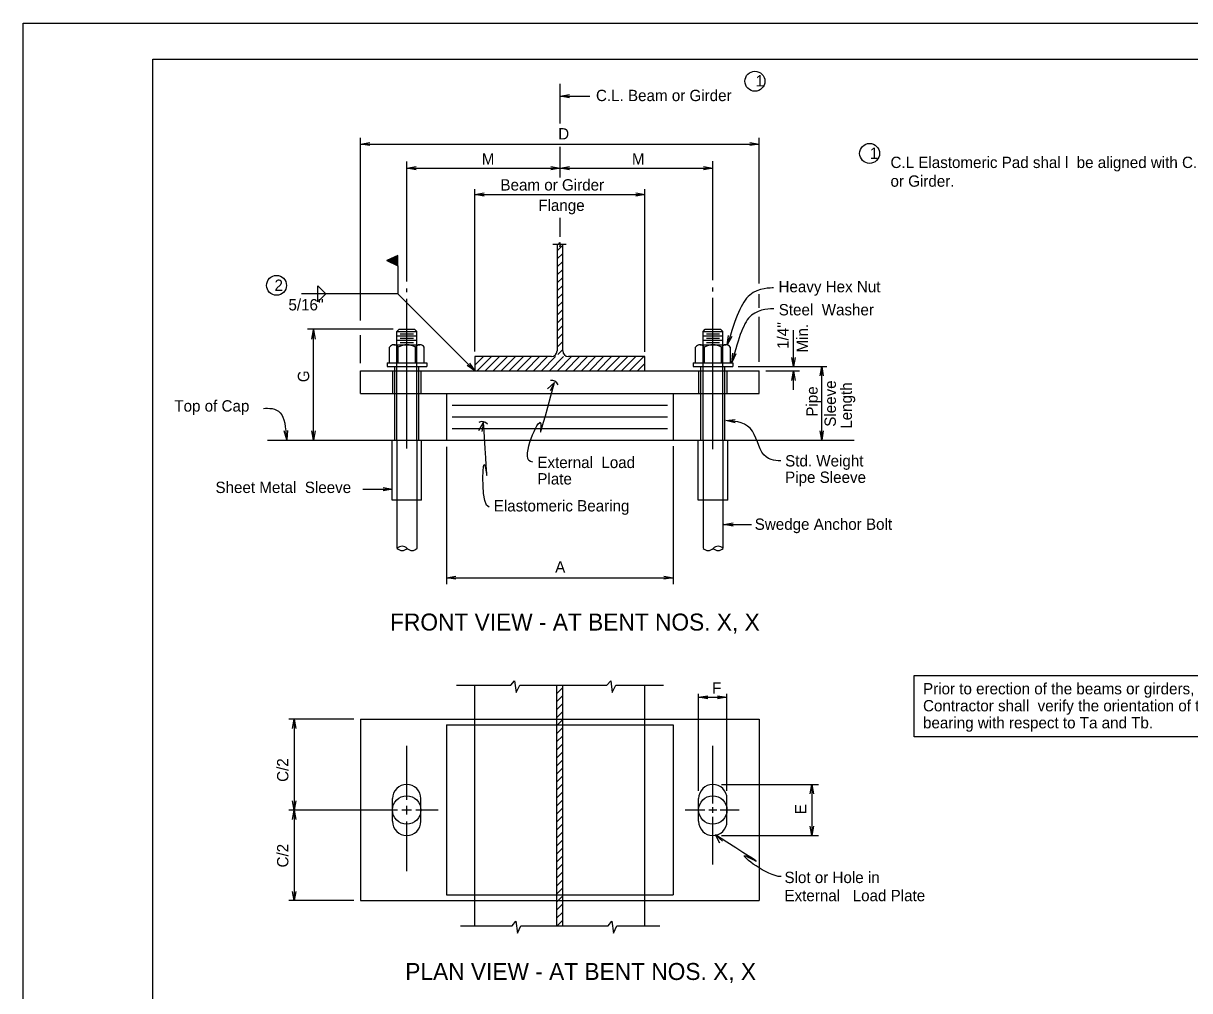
# Model space of a CAD drawing. Extents: x 113 to 232, y -103 to -27.
# Drawn here: x 176.59 to 185.16, y -74.86 to -67.75 of the extents above; entities that cross this region are included whole.
import ezdxf

# ---------------------------------------------------------------- set-up
doc = ezdxf.new("R2010")
doc.units = 0
for name, color, linetype in [('1', 7, 'Continuous'), ('B_Border', 7, 'Continuous'), ('B_Dimension', 7, 'Continuous'), ('B_No_Plot', 7, 'Continuous')]:
    doc.layers.add(name, color=color, linetype=linetype)

msp = doc.modelspace()

# ---------------------------------------------------------------- linework, layer by layer
at = {"layer": '1'}
for p, q in [((180.5342, -68.4846), (180.5342, -68.1923)), ((180.5342, -68.2835), (180.7515, -68.2835)), ((179.067, -69.933), (179.067, -68.5907)), ((181.997, -69.6603), (181.997, -68.5907)), ((179.067, -68.6354), (181.997, -68.6354)), ((180.5342, -68.8825), (180.5342, -68.6555)), ((179.407, -69.6472), (179.407, -68.7631)), ((181.657, -69.6364), (181.657, -68.7621)), ((179.407, -68.8121), (180.5342, -68.8121)), ((180.5342, -68.8121), (181.657, -68.8121)), ((179.907, -70.162), (179.907, -68.9673)), ((179.907, -69.0068), (181.1584, -69.0068)), ((181.157, -70.1644), (181.157, -68.9673)), ((180.5342, -69.3185), (180.5342, -69.178)), ((180.5238, -69.3728), (180.5318, -69.3587)), ((180.5318, -69.3587), (180.5318, -69.3918)), ((180.4803, -69.3728), (180.5238, -69.3728)), ((180.5113, -69.3728), (180.5113, -70.1571)), ((180.5318, -69.3918), (180.5379, -69.3728)), ((180.5379, -69.3728), (180.5783, -69.3728)), ((180.5528, -70.1571), (180.5528, -69.3728)), ((179.3414, -69.4552), (179.2604, -69.4929)), ((179.2604, -69.4929), (179.3414, -69.5306)), ((179.3414, -69.4552), (179.3414, -69.4545)), ((179.3414, -69.5306), (179.3414, -69.4552)), ((179.3414, -69.5306), (179.3414, -69.5611)), ((179.3414, -69.5611), (179.3414, -69.7373)), ((178.7515, -69.7963), (178.7515, -69.6783)), ((178.7515, -69.6783), (178.8105, -69.7373)), ((179.407, -69.7257), (179.407, -69.6982)), ((181.657, -69.7187), (181.657, -69.6913)), ((179.3414, -69.7373), (178.6323, -69.7373)), ((178.8105, -69.7373), (178.7515, -69.7963)), ((179.907, -70.3029), (179.3414, -69.7373)), ((179.407, -70.8751), (179.407, -69.7727)), ((181.657, -70.88), (181.657, -69.7658)), ((181.997, -69.8388), (181.997, -69.739)), ((181.997, -70.2356), (181.997, -69.907)), ((179.3064, -69.9975), (178.6752, -69.9975)), ((178.7213, -70.8134), (178.7213, -70.0011)), ((179.067, -70.2474), (179.067, -70.0414)), ((179.3504, -69.9975), (179.3341, -70.0138)), ((179.3341, -70.111), (179.3341, -70.0138)), ((179.3341, -70.0138), (179.4799, -70.0138)), ((179.3341, -70.0462), (179.4799, -70.0462)), ((179.3504, -69.9975), (179.4636, -69.9975)), ((179.3584, -70.0302), (179.4556, -70.0302)), ((179.4636, -69.9975), (179.4799, -70.0138)), ((179.4799, -70.111), (179.4799, -70.0138)), ((181.5841, -70.0138), (181.6004, -69.9975)), ((181.5841, -70.0138), (181.7299, -70.0138)), ((181.5841, -70.111), (181.5841, -70.0138)), ((181.5841, -70.0138), (181.7299, -70.0138)), ((181.5841, -70.0462), (181.7299, -70.0462)), ((181.6004, -69.9975), (181.7136, -69.9975)), ((181.6084, -70.0302), (181.7056, -70.0302)), ((181.7136, -69.9975), (181.7299, -70.0138)), ((181.7299, -70.111), (181.7299, -70.0138)), ((182.2483, -70.272), (182.2483, -70.0031)), ((179.2797, -70.2448), (179.2797, -70.1293)), ((179.3118, -70.111), (179.5025, -70.111)), ((179.3341, -70.0786), (179.4799, -70.0786)), ((179.3341, -70.8134), (179.3341, -70.111)), ((179.344, -70.2448), (179.344, -70.1293)), ((179.3584, -70.0626), (179.4556, -70.0626)), ((179.3584, -70.0949), (179.4556, -70.0949)), ((179.4702, -70.2448), (179.4702, -70.1293)), ((179.4799, -70.8134), (179.4799, -70.111)), ((179.5348, -70.2448), (179.5348, -70.1293)), ((181.5297, -70.2448), (181.5297, -70.1293)), ((181.5618, -70.111), (181.7525, -70.111)), ((181.5841, -70.0786), (181.7299, -70.0786)), ((181.5841, -70.8134), (181.5841, -70.111)), ((181.594, -70.2448), (181.594, -70.1293)), ((181.6084, -70.0626), (181.7056, -70.0626)), ((181.6084, -70.0949), (181.7056, -70.0949)), ((181.7202, -70.2448), (181.7202, -70.1293)), ((181.7299, -70.8134), (181.7299, -70.111)), ((181.7848, -70.2448), (181.7848, -70.1293)), ((180.4696, -70.1987), (179.907, -70.1987)), ((179.907, -70.1987), (179.907, -70.3029)), ((181.157, -70.1987), (180.5944, -70.1987)), ((181.157, -70.3029), (181.157, -70.1987)), ((179.067, -70.4696), (179.067, -70.3029)), ((179.067, -70.3029), (181.997, -70.3029)), ((179.2612, -70.2448), (179.5528, -70.2448)), ((179.2612, -70.2448), (179.2612, -70.2708)), ((179.2612, -70.2708), (179.5528, -70.2708)), ((179.3029, -70.4696), (179.3029, -70.3042)), ((179.3185, -70.3042), (179.3185, -70.2712)), ((179.3185, -70.4696), (179.3185, -70.3042)), ((179.4955, -70.3042), (179.4955, -70.2712)), ((179.4955, -70.4694), (179.4955, -70.3042)), ((179.5111, -70.4696), (179.5111, -70.3042)), ((179.5528, -70.2448), (179.5528, -70.2708)), ((181.5112, -70.2448), (181.8028, -70.2448)), ((181.5112, -70.2448), (181.5112, -70.2708)), ((181.5112, -70.2708), (181.8028, -70.2708)), ((181.5529, -70.4705), (181.5529, -70.3037)), ((181.5685, -70.3037), (181.5685, -70.2704)), ((181.5685, -70.4705), (181.5685, -70.3037)), ((181.7455, -70.3037), (181.7455, -70.2714)), ((181.7455, -70.4715), (181.7455, -70.3067)), ((181.7611, -70.4715), (181.7611, -70.3067)), ((181.8028, -70.2448), (181.8028, -70.2708)), ((181.8428, -70.2708), (182.494, -70.2708)), ((181.997, -70.4696), (181.997, -70.3029)), ((182.0449, -70.3029), (182.2939, -70.3029)), ((182.2483, -70.4429), (182.2483, -70.3053)), ((182.4563, -70.8134), (182.4563, -70.2708)), ((179.067, -70.4696), (181.997, -70.4696)), ((179.3185, -70.8134), (179.3185, -70.4696)), ((179.4955, -70.8134), (179.4955, -70.4694)), ((179.6986, -70.4696), (179.6986, -70.8134)), ((181.3654, -70.4696), (181.3654, -70.8134)), ((181.5685, -70.8134), (181.5685, -70.4705)), ((181.7455, -70.8134), (181.7455, -70.4715)), ((179.7404, -70.5556), (181.3236, -70.5556)), ((179.7404, -70.6416), (181.3236, -70.6416)), ((179.7404, -70.7275), (181.3236, -70.7275)), ((178.3829, -70.8134), (182.6957, -70.8134)), ((179.2985, -71.2537), (179.2985, -70.8134)), ((179.3341, -70.8134), (179.3341, -71.2537)), ((179.4799, -70.8134), (179.4799, -71.2537)), ((179.5155, -71.2537), (179.5155, -70.8134)), ((181.5485, -71.2537), (181.5485, -70.8134)), ((181.5841, -70.8134), (181.5841, -71.2537)), ((181.7299, -70.8134), (181.7299, -71.2537)), ((181.7655, -71.2537), (181.7655, -70.8134)), ((179.6986, -70.8609), (179.6986, -71.8713)), ((181.3654, -70.8564), (181.3654, -71.8713)), ((179.0841, -71.1729), (179.3001, -71.1729)), ((179.5155, -71.2537), (179.2985, -71.2537)), ((179.3341, -71.2537), (179.3341, -71.6102)), ((179.4799, -71.2537), (179.4799, -71.6101)), ((181.7655, -71.2537), (181.5485, -71.2537)), ((181.5841, -71.2537), (181.5841, -71.6067)), ((181.7299, -71.2537), (181.7299, -71.6069)), ((181.7368, -71.4334), (181.9395, -71.4334)), ((179.6986, -71.8237), (181.3654, -71.8237)), ((179.7723, -72.6138), (180.1718, -72.6138)), ((179.9058, -74.3826), (179.9058, -72.6137)), ((180.2363, -72.6138), (180.8779, -72.6138)), ((180.5099, -74.3826), (180.5099, -72.6137)), ((180.5516, -72.6137), (180.5516, -74.3826)), ((180.9425, -72.6138), (181.2935, -72.6138)), ((181.1558, -74.3826), (181.1558, -72.6137)), ((181.5516, -73.3897), (181.5516, -72.6771)), ((181.5516, -72.7033), (181.7599, -72.7033)), ((181.7599, -73.3897), (181.7599, -72.6771)), ((179.0178, -72.8649), (178.5404, -72.8649)), ((178.5775, -72.8649), (178.5775, -73.5332)), ((179.0658, -72.8649), (179.0658, -74.1983)), ((179.0658, -72.8649), (179.9032, -72.8649)), ((179.9032, -72.8649), (181.158, -72.8649)), ((181.158, -72.8649), (181.9958, -72.8649)), ((181.158, -72.8649), (181.9958, -72.8649)), ((181.9958, -72.8649), (181.9958, -74.1983)), ((179.6974, -72.9066), (179.6974, -74.1566)), ((179.6974, -72.9066), (181.3641, -72.9066)), ((181.3641, -72.9066), (181.3641, -74.1566)), ((179.4058, -73.4558), (179.4058, -73.0609)), ((181.6558, -73.4837), (181.6558, -73.0609)), ((181.7195, -73.3441), (182.433, -73.3441)), ((182.3846, -73.3441), (182.3846, -73.7191)), ((179.3016, -73.6149), (179.3016, -73.4483)), ((179.5099, -73.6149), (179.5099, -73.4483)), ((181.5516, -73.6149), (181.5516, -73.4483)), ((181.7599, -73.6149), (181.7599, -73.4483)), ((178.5404, -73.5316), (179.3383, -73.5316)), ((178.5775, -73.5332), (178.5775, -74.1983)), ((179.3697, -73.5316), (179.441, -73.5316)), ((179.4058, -73.5644), (179.4058, -73.501)), ((179.4723, -73.5316), (179.5099, -73.5316)), ((179.5099, -73.5316), (179.6369, -73.5316)), ((181.452, -73.5316), (181.5962, -73.5316)), ((181.6274, -73.5316), (181.6866, -73.5316)), ((181.6558, -73.5532), (181.6558, -73.5114)), ((181.7109, -73.5316), (181.7599, -73.5316)), ((181.7599, -73.5316), (181.8498, -73.5316)), ((179.4058, -73.9814), (179.4058, -73.6157)), ((181.6558, -73.9325), (181.6558, -73.5827)), ((181.7195, -73.7191), (182.433, -73.7191)), ((179.6974, -74.1566), (181.3641, -74.1566)), ((179.0178, -74.1983), (178.5404, -74.1983)), ((179.0658, -74.1983), (179.9032, -74.1983)), ((179.9032, -74.1983), (181.1545, -74.1983)), ((181.1545, -74.1983), (181.9958, -74.1983)), ((179.8006, -74.3826), (180.1798, -74.3826)), ((180.2444, -74.3826), (180.8859, -74.3826)), ((180.9505, -74.3826), (181.2653, -74.3826))]:
    msp.add_line(p, q, dxfattribs=at)
for points in [[(180.5164, -69.4162), (180.5476, -69.385)], [(180.5164, -69.4752), (180.5476, -69.444)], [(179.2614, -69.4933), (179.2614, -69.4925)], [(179.2657, -69.4954), (179.2657, -69.4905)], [(179.27, -69.4974), (179.27, -69.4885)], [(179.2743, -69.4993), (179.2743, -69.4865)], [(179.2786, -69.5013), (179.2786, -69.4845)], [(179.2829, -69.5033), (179.2829, -69.4825)], [(179.2873, -69.5054), (179.2873, -69.4805)], [(179.2915, -69.5074), (179.2915, -69.4785)], [(179.2958, -69.5093), (179.2958, -69.4765)], [(179.3002, -69.5113), (179.3002, -69.4745)], [(179.3044, -69.5133), (179.3044, -69.4725)], [(179.3088, -69.5154), (179.3088, -69.4705)], [(179.3131, -69.5174), (179.3131, -69.4684)], [(179.3173, -69.5193), (179.3173, -69.4664)], [(179.3217, -69.5213), (179.3217, -69.4644)], [(179.3259, -69.5233), (179.3259, -69.4624)], [(179.3303, -69.5254), (179.3303, -69.4605)], [(179.3346, -69.5274), (179.3346, -69.4584)], [(179.3388, -69.5293), (179.3388, -69.4564)], [(180.5164, -69.5341), (180.5476, -69.5029)], [(180.5164, -69.593), (180.5476, -69.5618)], [(180.5164, -69.6519), (180.5476, -69.6207)], [(180.5164, -69.7108), (180.5476, -69.6797)], [(180.5164, -69.7697), (180.5476, -69.7386)], [(180.5164, -69.8287), (180.5476, -69.7975)], [(180.5164, -69.8876), (180.5476, -69.8564)], [(180.5164, -69.9465), (180.5476, -69.9153)], [(180.5164, -70.0054), (180.5476, -69.9742)], [(180.5164, -70.0643), (180.5476, -70.0332)], [(180.5164, -70.1232), (180.5476, -70.0921)], [(179.907, -70.2613), (179.9696, -70.1987)], [(179.907, -70.2024), (179.9107, -70.1987)], [(179.9243, -70.3029), (180.0285, -70.1987)], [(179.9833, -70.3029), (180.0874, -70.1987)], [(180.0422, -70.3029), (180.1463, -70.1987)], [(180.1011, -70.3029), (180.2053, -70.1987)], [(180.16, -70.3029), (180.2642, -70.1987)], [(180.2189, -70.3029), (180.3231, -70.1987)], [(180.2778, -70.3029), (180.382, -70.1987)], [(180.3368, -70.3029), (180.441, -70.1987)], [(180.3957, -70.3029), (180.4999, -70.1987)], [(180.4547, -70.3029), (180.5588, -70.1987)], [(180.5136, -70.3029), (180.6178, -70.1987)], [(180.5164, -70.1822), (180.5476, -70.151)], [(180.5725, -70.3029), (180.6767, -70.1987)], [(180.6314, -70.3029), (180.7356, -70.1987)], [(180.6903, -70.3029), (180.7945, -70.1987)], [(180.7493, -70.3029), (180.8535, -70.1987)], [(180.8082, -70.3029), (180.9123, -70.1987)], [(180.8672, -70.3028), (180.9713, -70.1987)], [(180.926, -70.3029), (181.0303, -70.1987)], [(180.985, -70.3029), (181.0892, -70.1987)], [(181.0439, -70.3029), (181.1481, -70.1987)], [(179.4178, -70.3029), (179.4178, -70.3029)], [(179.5356, -70.3029), (179.5356, -70.3029)], [(179.5946, -70.3029), (179.5946, -70.3029)], [(181.1028, -70.3029), (181.157, -70.2487)], [(181.5504, -70.3029), (181.5504, -70.3029)], [(180.1718, -72.6138), (180.1991, -72.5813), (180.2112, -72.668), (180.2363, -72.6138)], [(180.8779, -72.6138), (180.9053, -72.5813), (180.9173, -72.668), (180.9425, -72.6138)], [(180.5099, -72.6758), (180.5516, -72.6342)], [(180.5099, -72.7347), (180.5516, -72.6931)], [(180.5099, -72.7937), (180.5516, -72.752)], [(180.5099, -72.8526), (180.5516, -72.8109)], [(180.5099, -72.9115), (180.5516, -72.8699)], [(180.5099, -72.9704), (180.5516, -72.9288)], [(180.5099, -73.0293), (180.5516, -72.9878)], [(180.5099, -73.0883), (180.5516, -73.0467)], [(180.5099, -73.1472), (180.5516, -73.1056)], [(180.5099, -73.2061), (180.5516, -73.1645)], [(180.5099, -73.265), (180.5516, -73.2234)], [(180.5099, -73.324), (180.5516, -73.2823)], [(180.5099, -73.3829), (180.5515, -73.3413)], [(180.5099, -73.4418), (180.5516, -73.4003)], [(180.5099, -73.5008), (180.5516, -73.4592)], [(180.5099, -73.5597), (180.5516, -73.5181)], [(180.5099, -73.6186), (180.5516, -73.577)], [(180.5099, -73.6775), (180.5516, -73.6359)], [(180.5099, -73.7364), (180.5516, -73.6948)], [(180.5099, -73.7953), (180.5516, -73.7538)], [(180.5099, -73.8543), (180.5516, -73.8127)], [(180.5099, -73.9133), (180.5516, -73.8716)], [(180.5099, -73.9722), (180.5516, -73.9306)], [(180.5099, -74.0311), (180.5516, -73.9895)], [(180.5099, -74.09), (180.5516, -74.0484)], [(180.5099, -74.1489), (180.5516, -74.1073)], [(180.5099, -74.2078), (180.5516, -74.1663)], [(180.5099, -74.2668), (180.5516, -74.2252)], [(180.5099, -74.3257), (180.5516, -74.2841)], [(180.1798, -74.3826), (180.2072, -74.3501), (180.2193, -74.4368), (180.2444, -74.3826)], [(180.5099, -74.3846), (180.5516, -74.343)], [(180.8859, -74.3826), (180.9133, -74.3501), (180.9253, -74.4368), (180.9505, -74.3826)]]:
    msp.add_lwpolyline(points, dxfattribs=at)
msp.add_lwpolyline([(183.1366, -72.5423), (186.0774, -72.5423), (186.0774, -72.9933), (183.1366, -72.9933)], close=True, dxfattribs=at)
for centre, radius in [((181.9655, -68.1738), 0.0733), ((182.8086, -68.7045), 0.0733), ((178.4489, -69.6745), 0.0733), ((179.4058, -73.5316), 0.1042), ((181.6558, -73.5316), 0.1042)]:
    msp.add_circle(centre, radius, dxfattribs=at)
for centre, radius, start, end in [((179.3119, -70.1484), 0.0375, 30.80861, 149.1914), ((179.4071, -70.229), 0.118, 57.68982, 122.31018), ((179.5025, -70.1486), 0.0376, 30.95728, 149.04272), ((181.5619, -70.1484), 0.0375, 30.80861, 149.1914), ((181.6571, -70.229), 0.118, 57.68982, 122.31018), ((181.7525, -70.1486), 0.0376, 30.95728, 149.04272), ((180.4696, -70.157), 0.0417, 270, 360), ((180.5945, -70.157), 0.0417, 180, 270), ((180.4706, -70.4244), 0.0513, 21.6992, 99.92259), ((179.9606, -70.7273), 0.0513, 40.39617, 118.61956), ((179.3722, -71.6433), 0.0504, 43.71346, 136.28654), ((181.6951, -71.6433), 0.0504, 43.71346, 136.28654), ((179.3722, -71.5736), 0.0504, 223.71346, 316.28654), ((179.4451, -71.5736), 0.0504, 223.71346, 316.28654), ((181.6222, -71.5736), 0.0504, 223.71346, 316.28654), ((181.6951, -71.5736), 0.0504, 223.71346, 316.28654), ((179.4058, -73.4482), 0.1042, 0, 180), ((181.6558, -73.4482), 0.1042, 0, 180), ((179.4058, -73.6149), 0.1042, 180, 0), ((181.6558, -73.6149), 0.1042, 180, 0)]:
    msp.add_arc(centre, radius, start, end, dxfattribs=at)
for points in [[(182.1019, -69.6937), (182.0853, -69.6931), (181.8981, -69.6902), (181.8273, -69.9102), (181.7627, -70.111)], [(182.1051, -69.8477), (182.0888, -69.8471), (181.9114, -69.8404), (181.8504, -70.0495), (181.7959, -70.2411)], [(180.3319, -70.9738), (180.23, -70.9738), (180.4923, -70.3881), (180.3319, -70.9738), (180.4923, -70.3881)], [(178.3524, -70.579), (178.3878, -70.5763), (178.5018, -70.5769), (178.5146, -70.7135), (178.5237, -70.8101)], [(180.0116, -71.3059), (179.9534, -71.3025), (179.9698, -70.6813), (180.0116, -71.3059), (179.9698, -70.6813)], [(182.1567, -70.9637), (182.1399, -70.9649), (182.0023, -70.971), (181.9673, -70.6785), (181.7968, -70.6712), (181.7516, -70.6692)], [(182.1587, -74.0218), (182.0508, -74.0188), (181.6756, -73.7152), (182.1587, -74.0218), (181.6756, -73.7152)]]:
    msp.add_open_spline(points, degree=3, dxfattribs=at)
at = {"layer": 'B_Border'}
for p, q in [((177.539, -68.0117), (198.6157, -68.0117)), ((177.539, -81.7084), (177.539, -68.0117)), ((177.5397, -81.7077), (177.5397, -68.0117))]:
    msp.add_line(p, q, dxfattribs=at)
at = {"layer": 'B_Dimension'}
for points in [[(180.6025, -68.2956), (180.5342, -68.2835), (180.6025, -68.2715)], [(179.1353, -68.6474), (179.067, -68.6354), (179.1353, -68.6233)], [(181.9287, -68.6233), (181.997, -68.6354), (181.9287, -68.6474)], [(179.4753, -68.8242), (179.407, -68.8121), (179.4753, -68.8001)], [(180.4659, -68.8001), (180.5342, -68.8121), (180.4659, -68.8242)], [(180.6025, -68.8242), (180.5342, -68.8121), (180.6025, -68.8001)], [(181.5887, -68.8001), (181.657, -68.8121), (181.5887, -68.8242)], [(179.9753, -69.0188), (179.907, -69.0068), (179.9753, -68.9947)], [(181.0901, -68.9947), (181.1584, -69.0068), (181.0901, -69.0188)], [(178.7092, -70.0694), (178.7213, -70.0011), (178.7333, -70.0694)], [(181.7951, -70.0496), (181.7627, -70.111), (181.7722, -70.0422)], [(181.8262, -70.1787), (181.7959, -70.2411), (181.803, -70.1721)], [(182.2604, -70.2037), (182.2483, -70.272), (182.2363, -70.2037)], [(179.8672, -70.2461), (179.907, -70.3029), (179.8502, -70.2631)], [(182.2363, -70.3736), (182.2483, -70.3053), (182.2604, -70.3736)], [(182.4442, -70.3391), (182.4563, -70.2708), (182.4683, -70.3391)], [(180.4408, -70.4347), (180.4923, -70.3881), (180.4599, -70.4495)], [(179.9361, -70.7419), (179.9698, -70.6813), (179.9588, -70.7498)], [(181.8194, -70.6842), (181.7516, -70.6692), (181.8204, -70.6601)], [(178.5293, -70.741), (178.5237, -70.8101), (178.5053, -70.7432)], [(178.7333, -70.7451), (178.7213, -70.8134), (178.7092, -70.7451)], [(182.4683, -70.7451), (182.4563, -70.8134), (182.4442, -70.7451)], [(179.2317, -71.1609), (179.3001, -71.1729), (179.2317, -71.185)], [(181.8051, -71.4455), (181.7368, -71.4334), (181.8051, -71.4214)], [(179.767, -71.8357), (179.6986, -71.8237), (179.767, -71.8116)], [(181.2971, -71.8116), (181.3654, -71.8237), (181.2971, -71.8357)], [(181.6199, -72.7153), (181.5516, -72.7033), (181.6199, -72.6912)], [(181.6916, -72.6912), (181.7599, -72.7033), (181.6916, -72.7153)], [(178.5655, -72.9332), (178.5775, -72.8649), (178.5896, -72.9332)], [(182.3726, -73.4124), (182.3846, -73.3441), (182.3966, -73.4124)], [(178.5896, -73.4648), (178.5775, -73.5332), (178.5655, -73.4648)], [(178.5655, -73.6015), (178.5775, -73.5332), (178.5896, -73.6015)], [(182.3966, -73.6508), (182.3846, -73.7191), (182.3726, -73.6508)], [(181.7083, -73.7764), (181.6756, -73.7152), (181.7272, -73.7615)], [(178.5896, -74.1299), (178.5775, -74.1983), (178.5655, -74.1299)]]:
    msp.add_lwpolyline(points, dxfattribs=at)
at = {"layer": 'B_No_Plot'}
msp.add_lwpolyline([(176.5874, -67.748), (198.9207, -67.748), (198.9207, -81.972), (176.5874, -81.972)], close=True, dxfattribs=at)

# ---------------------------------------------------------------- texts
at = {"layer": '1'}
for s, height, p in [('1', 0.0833, (181.9703, -68.2121)), ('C.L. Beam or Girder', 0.083334, (180.7972, -68.32)), ('D', 0.0833, (180.5197, -68.6019)), ('1', 0.0833, (182.8099, -68.7453)), ('M', 0.0833, (179.9576, -68.787)), ('M', 0.0833, (181.0615, -68.787)), ('C.L Elastomeric Pad shal l  be aligned with C.L. Beam', 0.083334, (182.9622, -68.8119)), ('Beam or Girder', 0.083334, (180.095, -68.9774)), ('or Girder.', 0.08333, (182.9622, -68.9494)), ('Flange', 0.08333, (180.373, -69.1273)), ('2', 0.0833, (178.4341, -69.7153)), ('Heavy Hex Nut', 0.083334, (182.139, -69.7253)), ("5/16''", 0.08333, (178.5363, -69.8587)), ('Steel  Washer', 0.083334, (182.1406, -69.8953)), ('Top of Cap', 0.08333, (177.6977, -70.6025)), ('External  Load ', 0.083334, (180.3661, -71.0177)), ('Std. Weight ', 0.083334, (182.1875, -71.0061)), ('Plate', 0.08333, (180.3661, -71.1386)), ('Pipe Sleeve', 0.083334, (182.1875, -71.1269)), ('Sheet Metal  Sleeve', 0.083334, (178, -71.2013)), ('Elastomeric Bearing', 0.083334, (180.0457, -71.3368)), ('Swedge Anchor Bolt', 0.083334, (181.9641, -71.472)), ('A', 0.0833, (180.4972, -71.7861)), ('FRONT VIEW - AT BENT NOS. X, X', 0.124834, (179.2835, -72.2124)), ('F', 0.0833, (181.6504, -72.6761)), ('Prior to erection of the beams or girders, the ', 0.083334, (183.2014, -72.6815)), ('Contractor shall  verify the orientation of the ', 0.083334, (183.2014, -72.8065)), ('bearing with respect to Ta and Tb.', 0.083334, (183.2014, -72.9315)), ('Slot or Hole in ', 0.083334, (182.1827, -74.0689)), ('External   Load Plate', 0.083334, (182.1827, -74.2022)), ('PLAN VIEW - AT BENT NOS. X, X', 0.124834, (179.3951, -74.7814))]:
    msp.add_text(s, height=height, dxfattribs=at).set_placement(p)
for s, height, p in [("1/4''", 0.08333, (182.2129, -70.1414)), ('Min.', 0.08333, (182.3553, -70.1684)), ('G', 0.0833, (178.6887, -70.3863)), ('Sleeve ', 0.08333, (182.5607, -70.7141)), ('Pipe', 0.08333, (182.4268, -70.6399)), ('Length', 0.08333, (182.6783, -70.7287)), ('C/2', 0.08333, (178.5358, -73.3249)), ('E', 0.0833, (182.3429, -73.5629)), ('C/2', 0.08333, (178.5358, -73.9541))]:
    msp.add_text(s, height=height, rotation=90, dxfattribs=at).set_placement(p)

doc.saveas('drawing.dxf')
